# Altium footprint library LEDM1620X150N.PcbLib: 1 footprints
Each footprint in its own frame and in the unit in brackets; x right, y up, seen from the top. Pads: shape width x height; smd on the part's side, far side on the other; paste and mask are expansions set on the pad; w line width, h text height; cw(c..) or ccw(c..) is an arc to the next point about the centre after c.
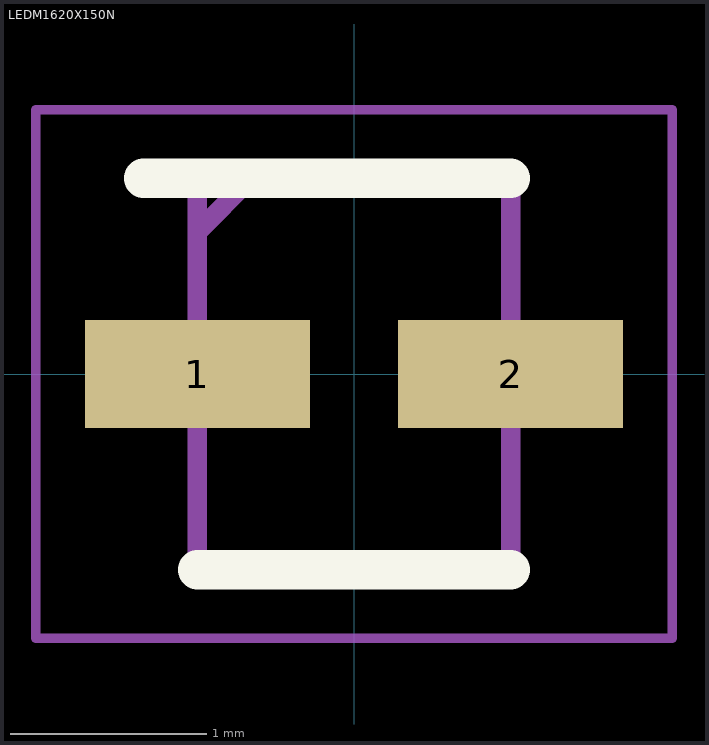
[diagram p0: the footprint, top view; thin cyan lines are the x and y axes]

## LEDM1620X150N [mm]
pads (2):
  rect 1.15x0.55 smd: 1(-0.8,0) 2(0.8,0)
Top Overlay:
  lines w0.2: -1.075,1 0.8,1 ; -0.8,-1 0.8,-1
Mechanical 15:
  lines w0.1: -0.8,0.725 -0.525,1 ; -0.8,-1 0.8,-1 0.8,1 -0.8,1 -0.8,-1
Mechanical 20:
  lines w0.05: -1.625,-1.35 1.625,-1.35 1.625,1.35 -1.625,1.35 -1.625,-1.35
